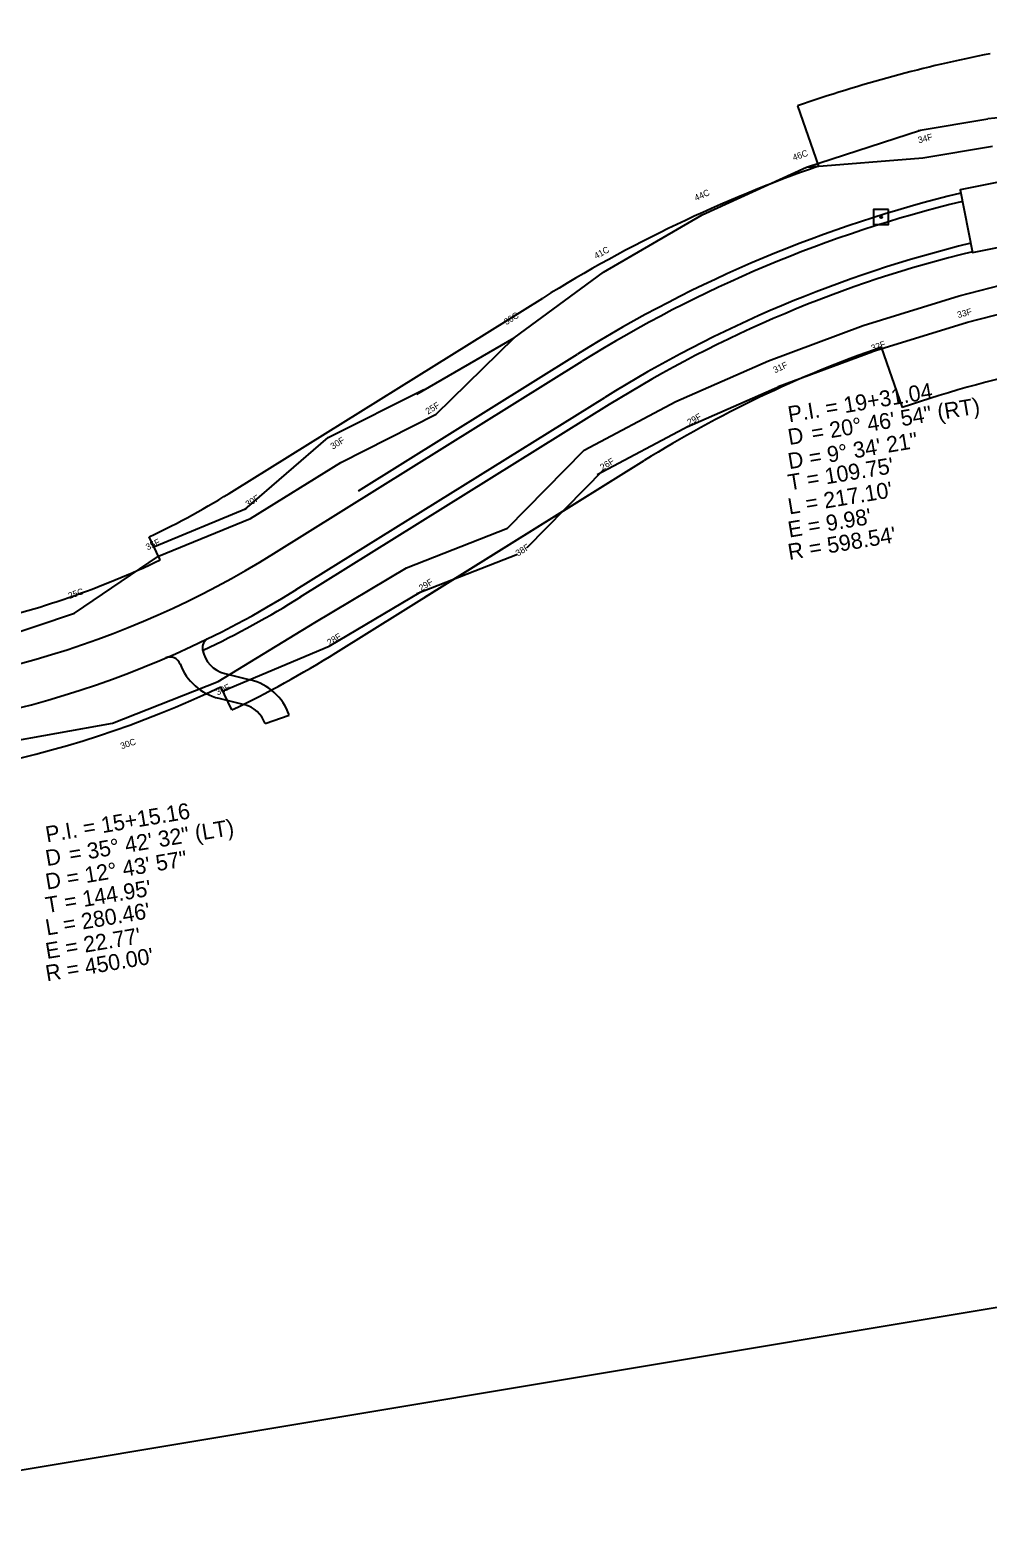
# Model space of a CAD drawing. Extents: x 1509010 to 1513406, y 898655 to 900162.
# Drawn here: x 1510516 to 1510966, y 899057 to 899765 of the extents above; entities that cross this region are included whole.
import ezdxf

# ---------------------------------------------------------------- set-up
doc = ezdxf.new("R2010")
doc.units = 0
for name, color, linetype in [('BR_CONCRETE', 7, 'Continuous'), ('RD_HC_Data', 7, 'Continuous'), ('RD_HC_Survey', 7, 'Continuous'), ('RD_PD_CstnLmt', 7, 'Continuous'), ('RD_PD_CstnLmt_TX', 7, 'Continuous'), ('RD_PD_DR_ErosCtrl', 7, 'Continuous'), ('RD_PD_Final_TrvlWay', 7, 'Continuous'), ('RD_PD_GR', 7, 'Continuous'), ('RD_PD_RW', 7, 'Continuous'), ('RD_Sketch2', 7, 'Continuous')]:
    doc.layers.add(name, color=color, linetype=linetype)

msp = doc.modelspace()

# ---------------------------------------------------------------- linework, layer by layer
at = {"layer": 'BR_CONCRETE'}
msp.add_lwpolyline([(1510972.24, 899694.19), (1510952.62, 899690.32), (1510958.43, 899660.89), (1510978.05, 899664.76)], close=True, dxfattribs=at)
at = {"layer": 'RD_HC_Survey'}
msp.add_lwpolyline([(1510919.06, 899681.11), (1510911.99, 899681.11), (1510911.99, 899674.04), (1510919.06, 899674.04)], close=True, dxfattribs=at)
msp.add_circle((1510915.53, 899677.57), 0.5, dxfattribs=at)
at = {"layer": 'RD_PD_CstnLmt'}
for p, q in [((1510935.04, 899705.37), (1510967.77, 899710.83)), ((1510880.52, 899701), (1510935.04, 899705.37)), ((1510831.57, 899678.62), (1510880.52, 899701)), ((1510785.24, 899651.62), (1510831.57, 899678.62)), ((1510743.26, 899620.77), (1510785.24, 899651.62)), ((1510952.21, 899640.58), (1510981.21, 899648.12)), ((1510907.04, 899626.65), (1510952.21, 899640.58)), ((1510862.69, 899610.07), (1510907.04, 899626.65)), ((1510706.64, 899585), (1510743.26, 899620.77)), ((1510819.16, 899590.93), (1510862.69, 899610.07)), ((1510776.11, 899568.1), (1510819.16, 899590.93)), ((1510661.83, 899562.35), (1510706.64, 899585)), ((1510740.07, 899531.4), (1510776.11, 899568.1)), ((1510619.4, 899535.98), (1510661.83, 899562.35)), ((1510576.24, 899518.24), (1510619.4, 899535.98)), ((1510692.75, 899512.77), (1510740.07, 899531.4)), ((1510536.79, 899491.54), (1510576.24, 899518.24)), ((1510649.73, 899487.2), (1510692.75, 899512.77)), ((1510491.93, 899476.37), (1510536.79, 899491.54)), ((1510604.3, 899459.42), (1510649.73, 899487.2)), ((1510554.72, 899439.85), (1510604.3, 899459.42)), ((1510502.35, 899430.39), (1510554.72, 899439.85))]:
    msp.add_line(p, q, dxfattribs=at)
at = {"layer": 'RD_PD_DR_ErosCtrl'}
for p, q in [((1510932.9, 899718.19), (1510965.63, 899723.65)), ((1510880.52, 899701), (1510934, 899718.33)), ((1510955.49, 899627.99), (1510984.48, 899635.54)), ((1510910.87, 899614.23), (1510956.04, 899628.15)), ((1510697.55, 899594.3), (1510743.26, 899620.77)), ((1510867.24, 899597.89), (1510911.59, 899614.47)), ((1510655.97, 899573.96), (1510700.77, 899596.6)), ((1510824.4, 899579.03), (1510867.93, 899598.17)), ((1510782.2, 899556.61), (1510825.25, 899579.44)), ((1510616.76, 899540.23), (1510655.97, 899573.96)), ((1510749.34, 899522.29), (1510785.38, 899558.99)), ((1510574.34, 899522.86), (1510617.5, 899540.61)), ((1510697.52, 899500.68), (1510744.83, 899519.3)), ((1510656.37, 899476.03), (1510699.4, 899501.6)), ((1510606.91, 899455.15), (1510656.37, 899476.03))]:
    msp.add_line(p, q, dxfattribs=at)
msp.add_arc((1510971.06, 899691.1), 33, 12.18941, 99.47431, dxfattribs=at)
at = {"layer": 'RD_PD_Final_TrvlWay'}
for p, q in [((1510630.4, 899519.53), (1510775.17, 899609.83)), ((1510640.98, 899502.56), (1510785.76, 899592.86)), ((1510607.39, 899463.19), (1510619.35, 899460.24)), ((1510604.52, 899451.54), (1510616.48, 899448.59)), ((1510626.32, 899439.68), (1510637.63, 899443.69))]:
    msp.add_line(p, q, dxfattribs=at)
for centre, radius, start, end in [((1511097.22, 899093.48), 608.54, 103.64138, 121.95202), ((1511097.22, 899093.48), 588.54, 103.72541, 121.95202), ((1510397.55, 899892.87), 440, 270.03596, 301.95202), ((1510397.55, 899892.87), 460, 270.03596, 301.95202), ((1510601.89, 899475.17), 5, 116.06865, 190.31309), ((1510581.72, 899465.89), 5, 20.56383, 113.33279), ((1510610.75, 899476.78), 14, 190.31309, 256.14412), ((1510610.75, 899476.78), 26, 200.56383, 256.14412), ((1510613.12, 899435), 26, 19.53947, 76.14412), ((1510613.12, 899435), 14, 19.53947, 76.14412)]:
    msp.add_arc(centre, radius, start, end, dxfattribs=at)
at = {"layer": 'RD_PD_GR'}
for p, q in [((1510670.14, 899549.03), (1510773.05, 899613.22)), ((1510787.87, 899589.46), (1510642.53, 899498.81))]:
    msp.add_line(p, q, dxfattribs=at)
for centre, radius, start, end in [((1511097.22, 899093.48), 612.54, 103.62446, 121.95202), ((1511097.22, 899093.48), 584.54, 103.74209, 121.95202), ((1510397.55, 899892.87), 464, 295.50075, 301.95202)]:
    msp.add_arc(centre, radius, start, end, dxfattribs=at)
at = {"layer": 'RD_PD_RW'}
for p, q in [((1510876.24, 899729.74), (1510886.08, 899701.4)), ((1510611.88, 899549.23), (1510756.65, 899639.52)), ((1510915.61, 899616.39), (1510925.45, 899588.05)), ((1510659.51, 899472.86), (1510804.28, 899563.16)), ((1510701.36, 899498.97), (1510804.28, 899563.16)), ((1510577.08, 899516.49), (1510571.91, 899527.32)), ((1510610.66, 899446.09), (1510605.49, 899456.92))]:
    msp.add_line(p, q, dxfattribs=at)
for centre, radius, start, end in [((1511097.22, 899093.48), 673.54, 101.17037, 109.15259), ((1511097.22, 899093.48), 643.54, 109.15259, 121.95202), ((1511097.22, 899093.48), 553.54, 109.15259, 121.95202), ((1511097.22, 899093.48), 523.54, 101.17037, 109.15259), ((1510397.55, 899892.87), 405, 295.50075, 301.95202), ((1510397.55, 899892.87), 417, 282.76836, 295.50075), ((1510397.55, 899892.87), 495, 295.50075, 301.95202), ((1510397.55, 899892.87), 483, 266.24308, 295.50075)]:
    msp.add_arc(centre, radius, start, end, dxfattribs=at)
at = {"layer": 'RD_Sketch2'}
msp.add_lwpolyline([(1510176.81, 899925.26), (1511597.17, 900162.3), (1511742.02, 899294.3), (1510321.67, 899057.27)], close=True, dxfattribs=at)

# ---------------------------------------------------------------- texts
at = {"layer": 'RD_HC_Data'}
for s, rotation, p in [('P.I. = 19+31.04', 9.4587, (1510872.42, 899581.11)), ('    = 20%%d 46\' 54" (RT)', 9.4587, (1510872.42, 899570.46)), ('D', 9.4587, (1510872.42, 899570.46)), ('D = 9%%d 34\' 21"', 9.4587, (1510872.42, 899559.12)), ("T = 109.75'", 9.4587, (1510872.42, 899549.12)), ("L = 217.10'", 9.4587, (1510872.42, 899537.84)), ("E = 9.98'", 9.4587, (1510872.42, 899526.99)), ("R = 598.54'", 9.4587, (1510872.42, 899516.49)), ('P.I. = 15+15.16', 9.51769, (1510523.88, 899383.83)), ('    = 35%%d 42\' 32" (LT)', 9.51769, (1510523.88, 899372.69)), ('D', 9.51769, (1510523.88, 899372.69)), ('D = 12%%d 43\' 57"', 9.51769, (1510523.88, 899361.66)), ("T = 144.95'", 9.51769, (1510523.88, 899350.62)), ("L = 280.46'", 9.51769, (1510523.88, 899340.14)), ("E = 22.77'", 9.51769, (1510523.88, 899329.09)), ("R = 450.00'", 9.51769, (1510523.88, 899318.59))]:
    msp.add_text(s, height=7.5, rotation=rotation, dxfattribs=at).set_placement(p)
at = {"layer": 'RD_PD_CstnLmt_TX'}
for s, rotation, p in [('34F', 14.84495, (1510933.24, 899712.14)), ('46C', 19.63122, (1510874.58, 899703.94)), ('44C', 24.41749, (1510828.68, 899684.99)), ('41C', 29.20376, (1510781.82, 899657.73)), ('36C', 31.95202, (1510739.55, 899626.71)), ('33F', 14.84495, (1510951.7, 899630.09)), ('32F', 19.63122, (1510911.4, 899614.41)), ('31F', 24.41749, (1510865.66, 899604.15)), ('25F', 31.95202, (1510702.79, 899584.72)), ('29F', 29.20376, (1510825.51, 899579.58)), ('30F', 31.95202, (1510658.13, 899568.29)), ('26F', 31.95202, (1510784.72, 899558.44)), ('30F', 31.86695, (1510618.23, 899541.15)), ('35F', 25.50075, (1510571.15, 899520.97)), ('38F', 31.95202, (1510745.04, 899518.09)), ('29F', 31.95202, (1510699.63, 899501.74)), ('25C', 19.13455, (1510534.5, 899498.15)), ('28F', 31.86695, (1510656.59, 899476.16)), ('30F', 25.50075, (1510604.02, 899452.83)), ('30C', 19.13455, (1510558.99, 899427.57))]:
    msp.add_text(s, height=3, rotation=rotation, dxfattribs=at).set_placement(p)

doc.saveas('drawing.dxf')
